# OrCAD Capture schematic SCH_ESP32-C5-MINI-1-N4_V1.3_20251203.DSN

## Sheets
1 01_DesignBlock: title: ESP32-C5-MINI-1-N4; rev: V1.3; note: <01_DesignBlock>
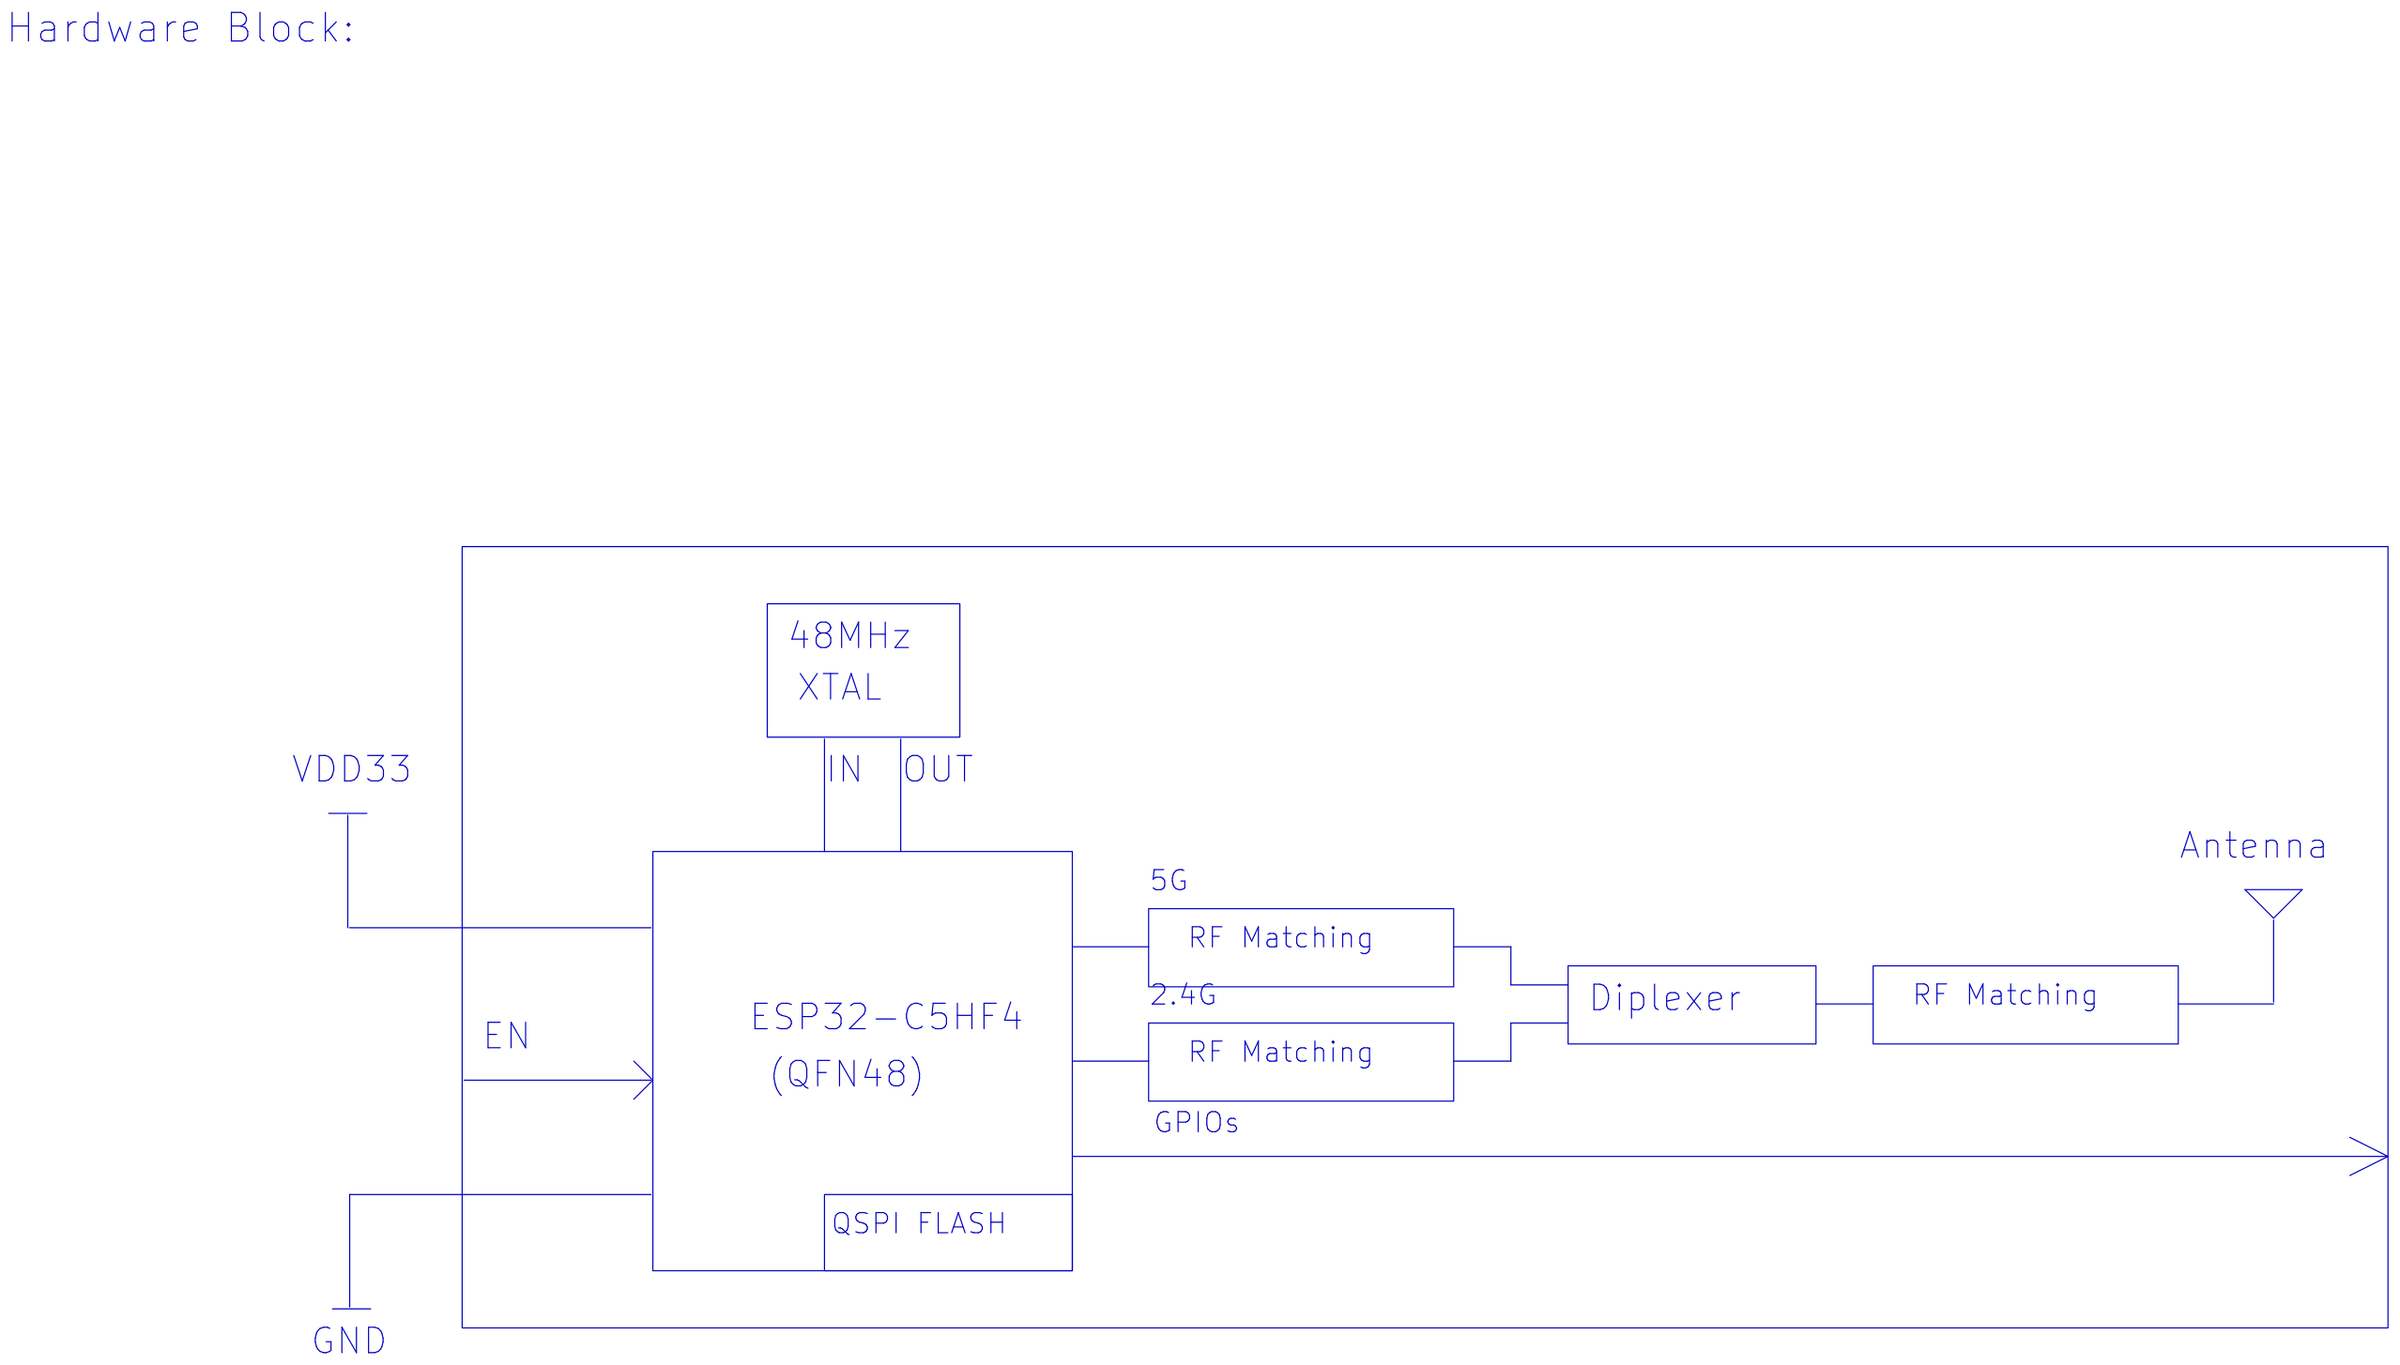
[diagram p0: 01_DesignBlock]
2 02_ESP32-C5-MINI-1-N4: size A3; title: <ESP32-C5-MINI-1-N4>; note: <02_ESP32-C5-MINI-1-N4>
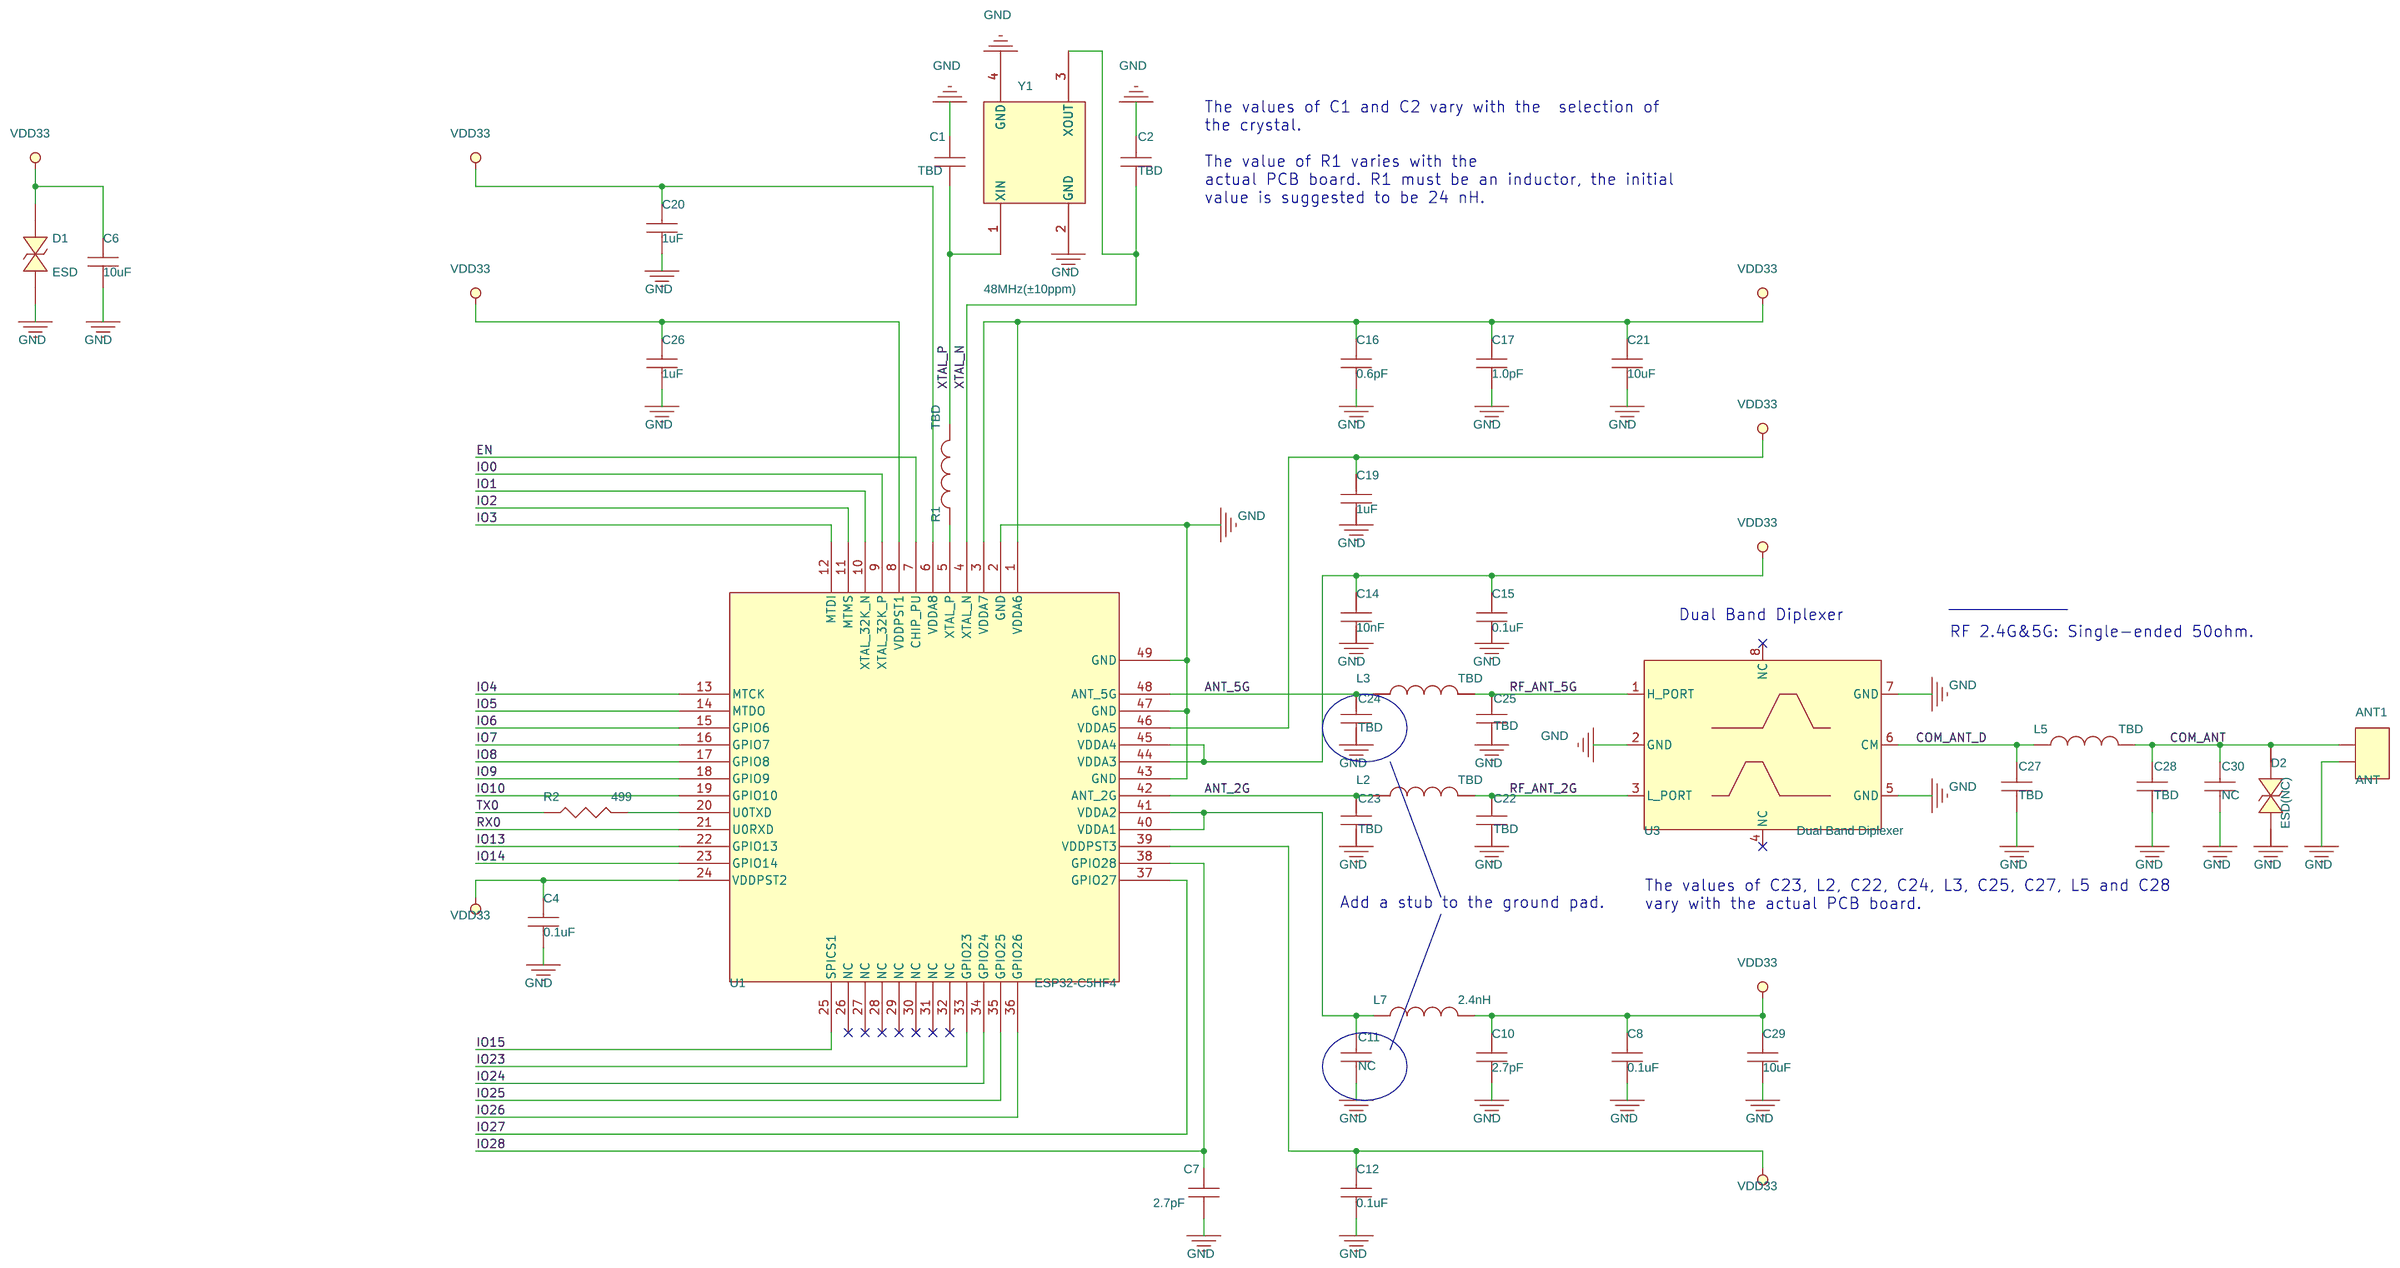
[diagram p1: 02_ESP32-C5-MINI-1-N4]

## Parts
ANT1  ANT  [DB-MINI-ANT-TYPEA2]
C1  TBD  [C0201]
C2  TBD  [C0201]
C4  0.1uF  [C0201]
C6  10uF  [C0402]
C7  2.7pF  [C0201]
C8  0.1uF  [C0201]
C10  2.7pF  [C0201]
C11  NC  [C0201]
C12  0.1uF  [C0201]
C14  10nF  [C0201]
C15  0.1uF  [C0201]
C16  0.6pF  [C0201]
C17  1.0pF  [C0201]
C19  1uF  [C0201]
C20  1uF  [C0201]
C21  10uF  [C0402]
C22  TBD  [C0201]
C23  TBD  [C0201]
C24  TBD  [C0201]
C25  TBD  [C0201]
C26  1uF  [C0201]
C27  TBD  [C0201]
C28  TBD  [C0201]
C29  10uF  [C0402]
C30  NC  [C0201]
D1  ESD  [SOD882]
D2  ESD(NC)  [DFN0603]
L2  TBD  [L0201]
L3  TBD  [L0201]
L5  TBD  [L0201]
L7  2.4nH  [L0201]
R1  TBD  [R0201]
R2  499  [R0201]
U1  ESP32-C5HF4  [QFN48_0P4_6_E4P7]
U3  Dual Band Diplexer  [DIPLEXER8_0P5_1P6X0P8]
Y1  48MHz(±10ppm)  [XTAL2016]

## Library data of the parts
ANT1 = CON2X1
C1 C2 C11 C22-C25 C27 C28 C30 = CAPACITOR
C4 C8 C12 C15 = CAPACITOR: CODE12: ES01.1.1.104.2.6.0.00; Part Number: ES01111042600000; Part Type: Capacitor
C6 C21 C29 = CAPACITOR: CODE12: ES01.1.2.106.2.7.0.00; Part Number: ES01121062700000; Part Type: Capacitor
C7 C10 = CAPACITOR: CODE12: ES01.1.1.2R7.6.2.2.00; Part Number: ES01112R76220000; Part Type: Capacitor
C14 = CAPACITOR: CODE12: ES01.1.1.103.3.6.2.00; Part Number: ES01111033620000; Part Type: Capacitor
C16 = CAPACITOR: CODE12: ES01.1.1.R60.6.2.2.00; Part Number: ES0111R606220000; Part Type: Capacitor
C17 = CAPACITOR: CODE12: ES01.1.1.1R0.6.2.2.00; Part Number: ES01111R06220000; Part Type: Capacitor
C19 C20 C26 = CAPACITOR: CODE12: ES01.1.1.105.2.7.0.00; Part Number: ES01111052700000; Part Type: Capacitor
D1 = DIODE_BI_DIR: CODE12: ES06.1.1.3.01.00000; Part Number: ES06113010000000; Part Type: Diode
D2 = DIODE_BI_DIR
L2 L3 L5 R1 = INDUCTOR
L7 = INDUCTOR: CODE12: ES02.1.1.2N4.0.2.001; Part Number: ES02112N40200100; Part Type: Inductor
R2 = RESISTOR: CODE12: ES03.1.1.4990.1.000; Part Number: ES03114990100002; Part Type: Resistor
U1 = ESP32-C5-QFN48_2: CODE12: ES00.10.C.2.N.3.1.000; Part Number: ES0010C2N3100000; Part Type: ESP ICs
U3 = LFD182G45DCHD481: CODE12: ES11.1.00.05.00000; Part Number: ES11100050000000
Y1 = XTAL_4P: CODE12: ES04.1.1.4802.0.1.00; Part Number: ES04114802010000; Part Type: Clock

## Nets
GND: ANT1.2 C1.2 C2.2 C4.2 C6.2 C7.2 C8.2 C10.2 C11.2 C12.2 C14.2 C15.2 C16.2 C17.2 C19.2 C20.2 C21.2 C22.2 C23.2 C24.2 C25.2 C26.2 C27.2 C28.2 C29.2 C30.2 D1.1 D2.2 U1.2(GND) U1.43(GND) U1.47(GND) U1.49(GND) U3.2(GND) U3.5(GND) U3.7(GND) Y1.2(GND) Y1.4(GND)
VDD33: C4.1 C6.1 C8.1 C10.1 C12.1 C14.1 C15.1 C16.1 C17.1 C19.1 C20.1 C21.1 C26.1 C29.1 D1.2 L7.2 U1.1(VDDA6) U1.3(VDDA7) U1.6(VDDA8) U1.8(VDDPST1) U1.24(VDDPST2) U1.39(VDDPST3) U1.44(VDDA3) U1.45(VDDA4) U1.46(VDDA5)
ANT_2G: C23.1 L2.1 U1.42(ANT_2G)
ANT_5G: C24.1 L3.1 U1.48(ANT_5G)
COM_ANT: ANT1.1 C28.1 C30.1 D2.1 L5.1
COM_ANT_D: C27.1 L5.2 U3.6(CM)
EN: U1.7(CHIP_PU)
IO0: U1.9(XTAL_32K_P)
IO1: U1.10(XTAL_32K_N)
IO2: U1.11(MTMS)
IO3: U1.12(MTDI)
IO4: U1.13(MTCK)
IO5: U1.14(MTDO)
IO6: U1.15(GPIO6)
IO7: U1.16(GPIO7)
IO8: U1.17(GPIO8)
IO9: U1.18(GPIO9)
IO10: U1.19(GPIO10)
IO13: U1.22(GPIO13)
IO14: U1.23(GPIO14)
IO15: U1.25(SPICS1)
IO23: U1.33(GPIO23)
IO24: U1.34(GPIO24)
IO25: U1.35(GPIO25)
IO26: U1.36(GPIO26)
IO27: U1.37(GPIO27)
IO28: C7.1 U1.38(GPIO28)
RF_ANT_2G: C22.1 L2.2 U3.3(L_PORT)
RF_ANT_5G: C25.1 L3.2 U3.1(H_PORT)
RX0: U1.21(U0RXD)
TX0: R2.1
XTAL_N: C2.1 U1.4(XTAL_N) Y1.3(XOUT)
XTAL_P: C1.1 R1.1 Y1.1(XIN)
N17781636: R2.2 U1.20(U0TXD)
N17781700: R1.2 U1.5(XTAL_P)
N17782209: C11.1 L7.1 U1.40(VDDA1) U1.41(VDDA2)

Not connected (* = marked no-connect by the designer): U1 26(NC)* 27(NC)* 28(NC)* 29(NC)* 30(NC)* 31(NC)* 32(NC)*; U3 4(NC)* 8(NC)*

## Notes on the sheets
sheet 1
- Hardware Block:
- 48MHz
- XTAL
- VDD33
- IN
- OUT
- Antenna
- 5G
- RF Matching
- 2.4G
- Diplexer
- RF Matching
- ESP32-C5HF4
- EN
- RF Matching
- (QFN48)
- GPIOs
- QSPI FLASH
- GND
sheet 2
- The values of C1 and C2 vary with the  selection of
  the crystal.
  The value of R1 varies with the
  actual PCB board. R1 must be an inductor, the initial
  value is suggested to be 24 nH.
- Dual Band Diplexer
- RF 2.4G&5G: Single-ended 50ohm.
- The values of C23, L2, C22, C24, L3, C25, C27, L5 and C28
  vary with the actual PCB board.
- Add a stub to the ground pad.
